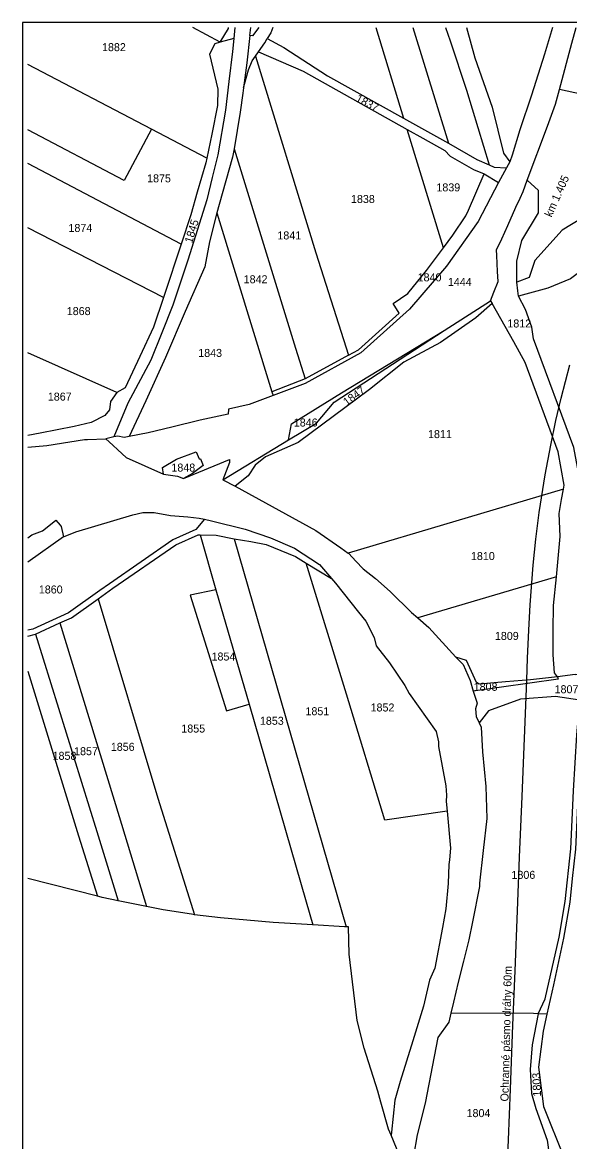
# Model space of a CAD drawing. Extents: x -583889 to -582839, y -1166553 to -1165068.
# Drawn here: x -583889 to -583410, y -1166047 to -1165068 of the extents above; entities that cross this region are included whole.
import ezdxf

# ---------------------------------------------------------------- set-up
doc = ezdxf.new("R2010")
doc.units = 0
for name, color, linetype in [('37', 7, 'Continuous'), ('_parcely přehledka', 7, 'Continuous'), ('Hranice parcel', 7, 'Continuous'), ('Parcelní čísla', 7, 'Continuous')]:
    doc.layers.add(name, color=color, linetype=linetype)

msp = doc.modelspace()

# ---------------------------------------------------------------- linework, layer by layer
at = {"layer": '37'}
msp.add_lwpolyline([(-583465.54, -1166090.53), (-583463.73, -1166045.43), (-583461.96, -1166001.15), (-583459.73, -1165944.95), (-583457.83, -1165897.51), (-583455.75, -1165845), (-583453.88, -1165797.97), (-583451.76, -1165745.07), (-583447.63, -1165643.26), (-583446.86, -1165623.99), (-583445.81, -1165599.54), (-583444.66, -1165577.37), (-583442.03, -1165542.78), (-583439.67, -1165520.04), (-583436.68, -1165496.55), (-583431.49, -1165463.54), (-583426.63, -1165437.64), (-583422.05, -1165416.22), (-583417.44, -1165396.54), (-583410.09, -1165367.4)], dxfattribs=at)
at = {"layer": '_parcely přehledka'}
msp.add_lwpolyline([(-583888.67, -1166552.78), (-582838.67, -1166552.78), (-582838.67, -1165067.78), (-583888.67, -1165067.78), (-583888.67, -1166552.78)], dxfattribs=at)
at = {"layer": 'Hranice parcel'}
for p, q in [((-583715.82, -1165085.15), (-583739.62, -1165072.33)), ((-583579.7, -1165072.33), (-583555.31, -1165151.49)), ((-583703.81, -1165081.91), (-583715.82, -1165085.15)), ((-583684.86, -1165097.43), (-583682.27, -1165093.64)), ((-583775.78, -1165161.12), (-583884.03, -1165104.76)), ((-583310.2, -1165149.72), (-583419.03, -1165126.58)), ((-583555.31, -1165151.49), (-583516.2, -1165173.54)), ((-583727.43, -1165186.55), (-583775.78, -1165161.12)), ((-583520.36, -1165264.96), (-583552.23, -1165161.46)), ((-583749.79, -1165261.93), (-583884.03, -1165191.27)), ((-583462.37, -1165189.75), (-583465.3, -1165195.14)), ((-583484.79, -1165200.39), (-583472.25, -1165207.93)), ((-583465.3, -1165195.14), (-583472.25, -1165207.93)), ((-583718.5, -1165234.51), (-583670.43, -1165390.93)), ((-583765.26, -1165308.42), (-583884.03, -1165247.62)), ((-583519.99, -1165337.31), (-583479.19, -1165311.26)), ((-583479.19, -1165311.26), (-583477.78, -1165313.78)), ((-583806.05, -1165391.64), (-583884.03, -1165356.82)), ((-583603.44, -1165358.82), (-583641.53, -1165379.75)), ((-583641.53, -1165379.75), (-583670.43, -1165390.93)), ((-583670.43, -1165390.93), (-583669.39, -1165394.23)), ((-583808.59, -1165430.5), (-583815.78, -1165432.24)), ((-583713.25, -1165467.9), (-583655.93, -1165433.01)), ((-583713.25, -1165467.9), (-583702.75, -1165473.63)), ((-583415.62, -1165476.12), (-583603.8, -1165532.05)), ((-583733.21, -1165515.97), (-583719.48, -1165564.15)), ((-583640.44, -1165540.93), (-583618.26, -1165554.37)), ((-583421.75, -1165552.72), (-583542.88, -1165588.73)), ((-583719.48, -1165564.15), (-583690.45, -1165664.16)), ((-583877.08, -1165602.99), (-583855.8, -1165593.22)), ((-583884.03, -1165604.66), (-583877.08, -1165602.99)), ((-583405.42, -1165638.41), (-583420.83, -1165640.2)), ((-583821.92, -1165832.64), (-583823.09, -1165832.34)), ((-583780.01, -1165841.28), (-583804.95, -1165836.2)), ((-583429.98, -1165935.47), (-583437.63, -1165935.06)), ((-583568.45, -1166036.07), (-583575.22, -1166012.56)), ((-583566.24, -1166041.4), (-583568.45, -1166036.07)), ((-583551.93, -1166075.89), (-583566.24, -1166041.4))]:
    msp.add_line(p, q, dxfattribs=at)
for points in [[(-583715.82, -1165085.15), (-583708.38, -1165072.99), (-583708.4, -1165072.33)], [(-583702.78, -1165072.33), (-583703.81, -1165081.91)], [(-583681.99, -1165072.33), (-583687.37, -1165079.52), (-583689.69, -1165079.18)], [(-583689.69, -1165079.18), (-583688.98, -1165072.33)], [(-583669.7, -1165072.33), (-583671.34, -1165076.83), (-583674.6, -1165081.96)], [(-583547.38, -1165072.33), (-583516.2, -1165173.54)], [(-583518.59, -1165072.33), (-583514.66, -1165083.97), (-583500.34, -1165127.02), (-583480.63, -1165192.3)], [(-583500.38, -1165072.33), (-583492.96, -1165098.9), (-583477.86, -1165141.87), (-583468.08, -1165182.16), (-583462.37, -1165189.75)], [(-583425.23, -1165072.33), (-583432.04, -1165095.47), (-583443.57, -1165131.51), (-583453.55, -1165161.91), (-583460.36, -1165183.86), (-583462.37, -1165189.75)], [(-583419.03, -1165126.58), (-583408.09, -1165086.08), (-583404.38, -1165072.33)], [(-583703.81, -1165081.91), (-583705.01, -1165093.13), (-583708.16, -1165119.58), (-583711.05, -1165144.58), (-583717.84, -1165183.67), (-583722.66, -1165203.37), (-583727.49, -1165223.07), (-583744.1, -1165275.81), (-583757.13, -1165315.32), (-583766.76, -1165339.34), (-583776.4, -1165363.37), (-583796.44, -1165401.06), (-583808.59, -1165430.5)], [(-583715.82, -1165085.15), (-583720.31, -1165086.49), (-583725.1, -1165095.68), (-583717.77, -1165126.09), (-583718, -1165140.48), (-583723.12, -1165165.52), (-583727.43, -1165186.55)], [(-583689.69, -1165079.18), (-583692.29, -1165103.21), (-583695.31, -1165125.06)], [(-583682.27, -1165093.64), (-583676.8, -1165085.62), (-583674.6, -1165081.96)], [(-583674.6, -1165081.96), (-583659.91, -1165089.88), (-583621.9, -1165114.45), (-583555.31, -1165151.49)], [(-583682.27, -1165093.64), (-583643.23, -1165110.39), (-583552.23, -1165161.46)], [(-583695.31, -1165125.06), (-583691.05, -1165109.16), (-583687.66, -1165101.5), (-583684.86, -1165097.43)], [(-583684.86, -1165097.43), (-583631.98, -1165269.4), (-583603.44, -1165358.82)], [(-583695.31, -1165125.06), (-583695.95, -1165129.63), (-583698.27, -1165146.41), (-583703.6, -1165178.45)], [(-583447.13, -1165205.68), (-583429.42, -1165158.54), (-583422.45, -1165139.19), (-583419.03, -1165126.58)], [(-583775.78, -1165161.12), (-583799.62, -1165206.05), (-583884.03, -1165161.64)], [(-583552.23, -1165161.46), (-583538.59, -1165169.11), (-583519.32, -1165179.92), (-583514.65, -1165184.96), (-583494.23, -1165196.62), (-583484.79, -1165200.39)], [(-583516.2, -1165173.54), (-583491.16, -1165187.69), (-583480.63, -1165192.3)], [(-583322.15, -1165168.47), (-583340.5, -1165179.46), (-583360.81, -1165200.75), (-583377.25, -1165221.89), (-583390.68, -1165233.74), (-583416.76, -1165249.61), (-583440.61, -1165276.22), (-583445.47, -1165291.1), (-583456.44, -1165295.04)], [(-583703.6, -1165178.45), (-583704.92, -1165185.84), (-583716.61, -1165227.24), (-583718.5, -1165234.51)], [(-583703.6, -1165178.45), (-583649.88, -1165352.67), (-583641.53, -1165379.75)], [(-583727.43, -1165186.55), (-583728.25, -1165190.56), (-583735.74, -1165216.34), (-583741.51, -1165236.18), (-583749.79, -1165261.93)], [(-583480.63, -1165192.3), (-583476.01, -1165194.31), (-583465.3, -1165195.14)], [(-583520.36, -1165264.96), (-583512.23, -1165253.9), (-583500.95, -1165237.01), (-583498.68, -1165232.05), (-583484.79, -1165200.39)], [(-583472.25, -1165207.93), (-583489.98, -1165241.85), (-583517.74, -1165281.11), (-583550.24, -1165318.78), (-583592.82, -1165357.01), (-583641.36, -1165383.65), (-583669.39, -1165394.23)], [(-583479.19, -1165311.26), (-583476.42, -1165303.92), (-583472.55, -1165294.46), (-583473.2, -1165285.59), (-583473.93, -1165271.71), (-583474.02, -1165266.7), (-583469.49, -1165257.18), (-583464.2, -1165245.36), (-583457.16, -1165229.52), (-583453.53, -1165221.51), (-583450.9, -1165215.7), (-583447.13, -1165205.68)], [(-583456.44, -1165295.04), (-583456.33, -1165276.69), (-583451.99, -1165258.51), (-583437.4, -1165234.32), (-583437.26, -1165214.82), (-583447.13, -1165205.68)], [(-583327.43, -1165211.57), (-583337.15, -1165221.16), (-583345.28, -1165232.38), (-583356.63, -1165240.96), (-583373.5, -1165261.36), (-583381.99, -1165269.78), (-583390.9, -1165278.52), (-583409.51, -1165292.26), (-583429.18, -1165300.2), (-583454.83, -1165307.19)], [(-583718.5, -1165234.51), (-583725.08, -1165259.67), (-583729.04, -1165281.56), (-583746.2, -1165320.59), (-583763.39, -1165360.97), (-583780.61, -1165398.76), (-583795.22, -1165430.08)], [(-583749.79, -1165261.93), (-583754.99, -1165277.68), (-583759.38, -1165290.95), (-583765.26, -1165308.42)], [(-583603.44, -1165358.82), (-583594.86, -1165354.14), (-583559.26, -1165322.11), (-583564.3, -1165313.84), (-583551.65, -1165304.88), (-583535.32, -1165284.91), (-583520.36, -1165264.96)], [(-583454.83, -1165307.19), (-583455.42, -1165302.7), (-583456.44, -1165295.04)], [(-583765.26, -1165308.42), (-583774.02, -1165334.53), (-583785.93, -1165360.04), (-583798.74, -1165387.49), (-583806.05, -1165391.64)], [(-583394.35, -1165470.85), (-583401.02, -1165469.37), (-583406.34, -1165439.81), (-583441.73, -1165344.5), (-583443.26, -1165334.4), (-583448.82, -1165319.07), (-583454.83, -1165307.19)], [(-583477.78, -1165313.78), (-583492.12, -1165326.39), (-583522.97, -1165347.85), (-583555.26, -1165365.02), (-583585.2, -1165388.92), (-583647.38, -1165435.26), (-583676.04, -1165447.98), (-583685.25, -1165455.04), (-583691.36, -1165464.4), (-583702.75, -1165473.63)], [(-583415.62, -1165476.12), (-583415.02, -1165472.65), (-583420.22, -1165443.6), (-583448.97, -1165365.39), (-583458.92, -1165347.2), (-583477.78, -1165313.78)], [(-583655.93, -1165433.01), (-583653.31, -1165418.98), (-583609.64, -1165391.73), (-583519.99, -1165337.31)], [(-583655.93, -1165433.01), (-583631.51, -1165418.42), (-583615.96, -1165400.02), (-583519.99, -1165337.31)], [(-583806.05, -1165391.64), (-583811.53, -1165399.43), (-583812.39, -1165406.78), (-583816.68, -1165411.64), (-583828.59, -1165417.87), (-583843.48, -1165421.37), (-583873.21, -1165427.21), (-583884.03, -1165429.34)], [(-583669.39, -1165394.23), (-583690.29, -1165402.12), (-583708.45, -1165406.08), (-583708.62, -1165410.54), (-583733.09, -1165415.85), (-583757.87, -1165421.89), (-583778.58, -1165426.97), (-583795.22, -1165430.08)], [(-583884.03, -1165439.32), (-583867.22, -1165438.01), (-583847.08, -1165434.66), (-583834.41, -1165432.61), (-583831.71, -1165432.56), (-583815.78, -1165432.24)], [(-583815.78, -1165432.24), (-583809.67, -1165437.75), (-583805.18, -1165441.81), (-583797.88, -1165448.39), (-583765.25, -1165462.95)], [(-583795.22, -1165430.08), (-583799.7, -1165430.92), (-583805.22, -1165429.68), (-583808.59, -1165430.5)], [(-583765.25, -1165462.95), (-583766.09, -1165457.07), (-583753.93, -1165449.79), (-583736.74, -1165443.57), (-583734.14, -1165449.73), (-583732.92, -1165449.76), (-583730.46, -1165455.46), (-583740, -1165462.35), (-583747.65, -1165466.82)], [(-583747.65, -1165466.82), (-583707.69, -1165450.07), (-583707.69, -1165452.8), (-583713.25, -1165467.9)], [(-583765.25, -1165462.95), (-583752.99, -1165464.84), (-583747.65, -1165466.82)], [(-583702.75, -1165473.63), (-583631.95, -1165512.27), (-583610.25, -1165527.42), (-583603.8, -1165532.05)], [(-583421.75, -1165552.72), (-583418.41, -1165517.42), (-583419.25, -1165497.44), (-583417.19, -1165485.32), (-583415.62, -1165476.12)], [(-583852.84, -1165517.96), (-583841.81, -1165513.57), (-583792.02, -1165498.71), (-583783.27, -1165496.64), (-583773.53, -1165496.7), (-583759.18, -1165499.18), (-583743.94, -1165500.5), (-583733.96, -1165501.55), (-583729.44, -1165502.52)], [(-583729.44, -1165502.52), (-583737.13, -1165511.45), (-583757.05, -1165520.41), (-583812.42, -1165558.83), (-583821.05, -1165564.92), (-583848.32, -1165584.28), (-583879.47, -1165598.58), (-583884.03, -1165599.62)], [(-583884.03, -1165518.63), (-583880.45, -1165516.15), (-583871.04, -1165512.47), (-583861.15, -1165504.68), (-583859.41, -1165503.31), (-583855.73, -1165507.58), (-583854.66, -1165508.82), (-583852.84, -1165517.96)], [(-583729.44, -1165502.52), (-583723.45, -1165503.81), (-583693.75, -1165511.27), (-583671.65, -1165518.59), (-583650.76, -1165527.82), (-583628.98, -1165542.04), (-583618.26, -1165554.37)], [(-583822.49, -1165572.22), (-583809.53, -1165562.91), (-583754.58, -1165524.78), (-583734.84, -1165516.01), (-583733.21, -1165515.97)], [(-583733.21, -1165515.97), (-583719.34, -1165516.31), (-583703.35, -1165519.71)], [(-583852.84, -1165517.96), (-583884.03, -1165540.08)], [(-583703.35, -1165519.71), (-583654.39, -1165689.39), (-583605.43, -1165859.07)], [(-583703.35, -1165519.71), (-583688.99, -1165522), (-583675.49, -1165524.68), (-583649.9, -1165535.2), (-583640.44, -1165540.93)], [(-583603.8, -1165532.05), (-583603.27, -1165532.43), (-583597.03, -1165539.1), (-583590.78, -1165545.76), (-583579.84, -1165554.27), (-583567.14, -1165565.76), (-583548.31, -1165584.01), (-583542.88, -1165588.73)], [(-583517.36, -1165757.73), (-583571.63, -1165765.62), (-583605.33, -1165655.58), (-583640.44, -1165540.93)], [(-583618.26, -1165554.37), (-583614.81, -1165558.32), (-583594.71, -1165583.65), (-583588.42, -1165591.55), (-583580.97, -1165605.8), (-583579.42, -1165613.24), (-583567.62, -1165627.95), (-583554.32, -1165648.02), (-583550.34, -1165655.03), (-583526.72, -1165688.02), (-583524.66, -1165697.3), (-583524.81, -1165701.28), (-583518.36, -1165735.56), (-583517.9, -1165743.74), (-583518.13, -1165749.48), (-583517.36, -1165757.73)], [(-583420.83, -1165640.2), (-583423.48, -1165636.82), (-583424.67, -1165621.14), (-583424.4, -1165599.47), (-583424.12, -1165577.81), (-583421.75, -1165552.72)], [(-583719.48, -1165564.15), (-583741.94, -1165568.88), (-583710.14, -1165670.14), (-583690.45, -1165664.16)], [(-583855.8, -1165593.22), (-583845.83, -1165588.64), (-583822.49, -1165572.22)], [(-583822.49, -1165572.22), (-583770.36, -1165746.36), (-583738.18, -1165848.42)], [(-583855.8, -1165593.22), (-583804.04, -1165762.63), (-583780.01, -1165841.28)], [(-583542.88, -1165588.73), (-583533.31, -1165597.07), (-583509.78, -1165623.06)], [(-583877.08, -1165602.99), (-583823.69, -1165775.61), (-583804.95, -1165836.2)], [(-583420.83, -1165640.2), (-583444.47, -1165642.96), (-583466.11, -1165644.8), (-583489.37, -1165646.78), (-583491.58, -1165645.28), (-583500.37, -1165626.09), (-583509.78, -1165623.06)], [(-583509.78, -1165623.06), (-583503.29, -1165629.64), (-583497.15, -1165643.66), (-583494.35, -1165652.77)], [(-583884.03, -1165635.34), (-583839.48, -1165779.37), (-583823.09, -1165832.34)], [(-583420.83, -1165640.2), (-583420.13, -1165642.5), (-583494.35, -1165652.77)], [(-583405.42, -1165638.41), (-583394.48, -1165637.13), (-583393.83, -1165639.42), (-583399.74, -1165691.26), (-583402.75, -1165740.2), (-583405.14, -1165791.1), (-583407.9, -1165816.75), (-583410.07, -1165837.49), (-583415.38, -1165868.98), (-583424.37, -1165909.91), (-583429.98, -1165935.47)], [(-583494.35, -1165652.77), (-583491.08, -1165663.43), (-583492.56, -1165668.46), (-583491.84, -1165674.97), (-583489.23, -1165680.56)], [(-583690.45, -1165664.16), (-583640.48, -1165837.32), (-583634.72, -1165857.29)], [(-583437.63, -1165935.06), (-583431.38, -1165922.1), (-583419.31, -1165868.22), (-583414.03, -1165836.86), (-583409.13, -1165790.79), (-583406.74, -1165739.98), (-583403.73, -1165691.01), (-583401.29, -1165660.74), (-583422.41, -1165657.63), (-583453.17, -1165659.96), (-583481.05, -1165670.05), (-583489.23, -1165680.56)], [(-583489.23, -1165680.56), (-583487.51, -1165684.26), (-583486.43, -1165705.91), (-583483.46, -1165736.23), (-583482.45, -1165764.15), (-583485.79, -1165792.34), (-583489.01, -1165820.82), (-583488.83, -1165823.76), (-583495.04, -1165854.79), (-583498.41, -1165870.54), (-583503.02, -1165889.04), (-583507.62, -1165907.55), (-583511.73, -1165925.04), (-583514, -1165934.51)], [(-583517.36, -1165757.73), (-583514.32, -1165790.16), (-583515.07, -1165800.5), (-583515.83, -1165804.41), (-583516.39, -1165821.2), (-583518.41, -1165843.31), (-583521.2, -1165859.69), (-583528.03, -1165895.13), (-583532.66, -1165905.77), (-583538.01, -1165928.56), (-583547.33, -1165958.68), (-583558.27, -1165994.28), (-583562.85, -1166010.78), (-583565.88, -1166038.71), (-583566.24, -1166041.4)], [(-583823.09, -1165832.34), (-583884.03, -1165816.82)], [(-583804.95, -1165836.2), (-583819, -1165833.34), (-583821.92, -1165832.64)], [(-583738.18, -1165848.42), (-583740.78, -1165848.11), (-583765.43, -1165844.25), (-583780.01, -1165841.28)], [(-583634.72, -1165857.29), (-583669.38, -1165855.17), (-583715.58, -1165851.13), (-583738.18, -1165848.42)], [(-583605.43, -1165859.07), (-583606.97, -1165858.98), (-583634.72, -1165857.29)], [(-583575.22, -1166012.56), (-583577.98, -1166002.97), (-583589.73, -1165965.16), (-583595.87, -1165940.9), (-583603.04, -1165883.03), (-583603.5, -1165859.19), (-583605.43, -1165859.07)], [(-583514, -1165934.51), (-583515.84, -1165942.53), (-583525.33, -1165956.01), (-583536.41, -1166013.21), (-583543.31, -1166041.15), (-583546.64, -1166059.79)], [(-583437.63, -1165935.06), (-583441.82, -1165934.91), (-583514, -1165934.51)], [(-583437.63, -1165935.06), (-583442.76, -1165962.33), (-583444.67, -1165983.77), (-583443.42, -1166004.77), (-583439.8, -1166018.02), (-583429.88, -1166045.64), (-583424.27, -1166085.25), (-583423.21, -1166090.9), (-583424.08, -1166118.73)], [(-583429.98, -1165935.47), (-583433.28, -1165950.47), (-583437.28, -1165981.91), (-583433.06, -1166016.1), (-583415.29, -1166060.7), (-583423.45, -1166118.73)]]:
    msp.add_lwpolyline(points, dxfattribs=at)

# ---------------------------------------------------------------- texts
for s, rotation, p in [('km 1.405', 65.91964, (-583426.03, -1165238.72)), ('Ochranné pásmo dráhy 60m', 88.52387, (-583463.68, -1166011.94))]:
    msp.add_text(s, height=7, rotation=rotation).set_placement(p)
at = {"layer": 'Parcelní čísla'}
for s, p in [('1882', (-583819.03, -1165092.94)), ('1875', (-583779.62, -1165207.72)), ('1839', (-583526.63, -1165215.62)), ('1838', (-583601.31, -1165225.79)), ('1874', (-583848.39, -1165251.11)), ('1841', (-583665.7, -1165257.68)), ('1842', (-583695.17, -1165296.01)), ('1840', (-583543.06, -1165294.36)), ('1444', (-583516.59, -1165298.32)), ('1868', (-583849.87, -1165323.87)), ('1812', (-583464.59, -1165334.69)), ('1843', (-583734.9, -1165360.45)), ('1867', (-583866.43, -1165398.68)), ('1846', (-583651.34, -1165421.33)), ('1811', (-583533.96, -1165431.47)), ('1848', (-583758.37, -1165460.76)), ('1810', (-583496.42, -1165538.17)), ('1860', (-583874.3, -1165567.42)), ('1809', (-583475.47, -1165608.04)), ('1854', (-583723.27, -1165626.07)), ('1808', (-583494.02, -1165652.54)), ('1807', (-583423.28, -1165654.68)), ('1852', (-583584.19, -1165670.65)), ('1851', (-583641.14, -1165673.92)), ('1855', (-583749.68, -1165689.08)), ('1853', (-583680.97, -1165682.29)), ('1857', (-583843.46, -1165708.89)), ('1856', (-583811.35, -1165705.08)), ('1858', (-583862.27, -1165712.95)), ('1806', (-583461, -1165817.08)), ('1804', (-583500.24, -1166025.53))]:
    msp.add_text(s, height=7, dxfattribs=at).set_placement(p)
for s, rotation, p in [('1837', 332, (-583597.93, -1165136.47)), ('1845', 73, (-583740.33, -1165261.43)), ('1847', 36, (-583605.07, -1165403.53)), ('1803', 92, (-583435.12, -1166007.41))]:
    msp.add_text(s, height=7, rotation=rotation, dxfattribs=at).set_placement(p)

doc.saveas('drawing.dxf')
